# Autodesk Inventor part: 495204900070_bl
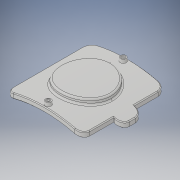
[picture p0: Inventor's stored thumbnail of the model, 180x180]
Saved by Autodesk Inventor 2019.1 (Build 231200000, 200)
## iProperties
Created: 2023-08
Part Number: 495204900070_bl
Material: Generic
Description: Repair Saddle 250-900mm
Document SubType Name: Modeling
Designer: Kirill
Density: 1 g/cm^3
Appearance: Default
Author: Kirill
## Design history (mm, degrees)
derived "49520.ipt"
feature "Solid1::49520.ipt" dims "ScaleForDerivedMember" = 10
tag "TaggingFeature1"
body "Solid1"
other parameters: "d1" = 18 [user parameter], "d2" = 274.5 [user parameter], "d4" = 0 [user parameter], "d5" = 486 [user parameter], "d6" = 183 [user parameter], "d8" = 0 [user parameter], "d11" = 0 [user parameter], "d12" = 6.1 [user parameter], "d16" = 135 [user parameter], "d19" = 5 deg [user parameter], "d21" = 14 [user parameter], "d22" = 18 [user parameter], "d23" = 0 [user parameter], "d25" = 7 [user parameter], "d27" = 0 [user parameter], "d28" = 305 [user parameter], "d29" = 75 [user parameter], "d30" = 0 [user parameter], "d31" = 27 [user parameter], "d32" = 2.7 [user parameter], "B_" = 305 [user parameter], "d24" = 14 [user parameter]
